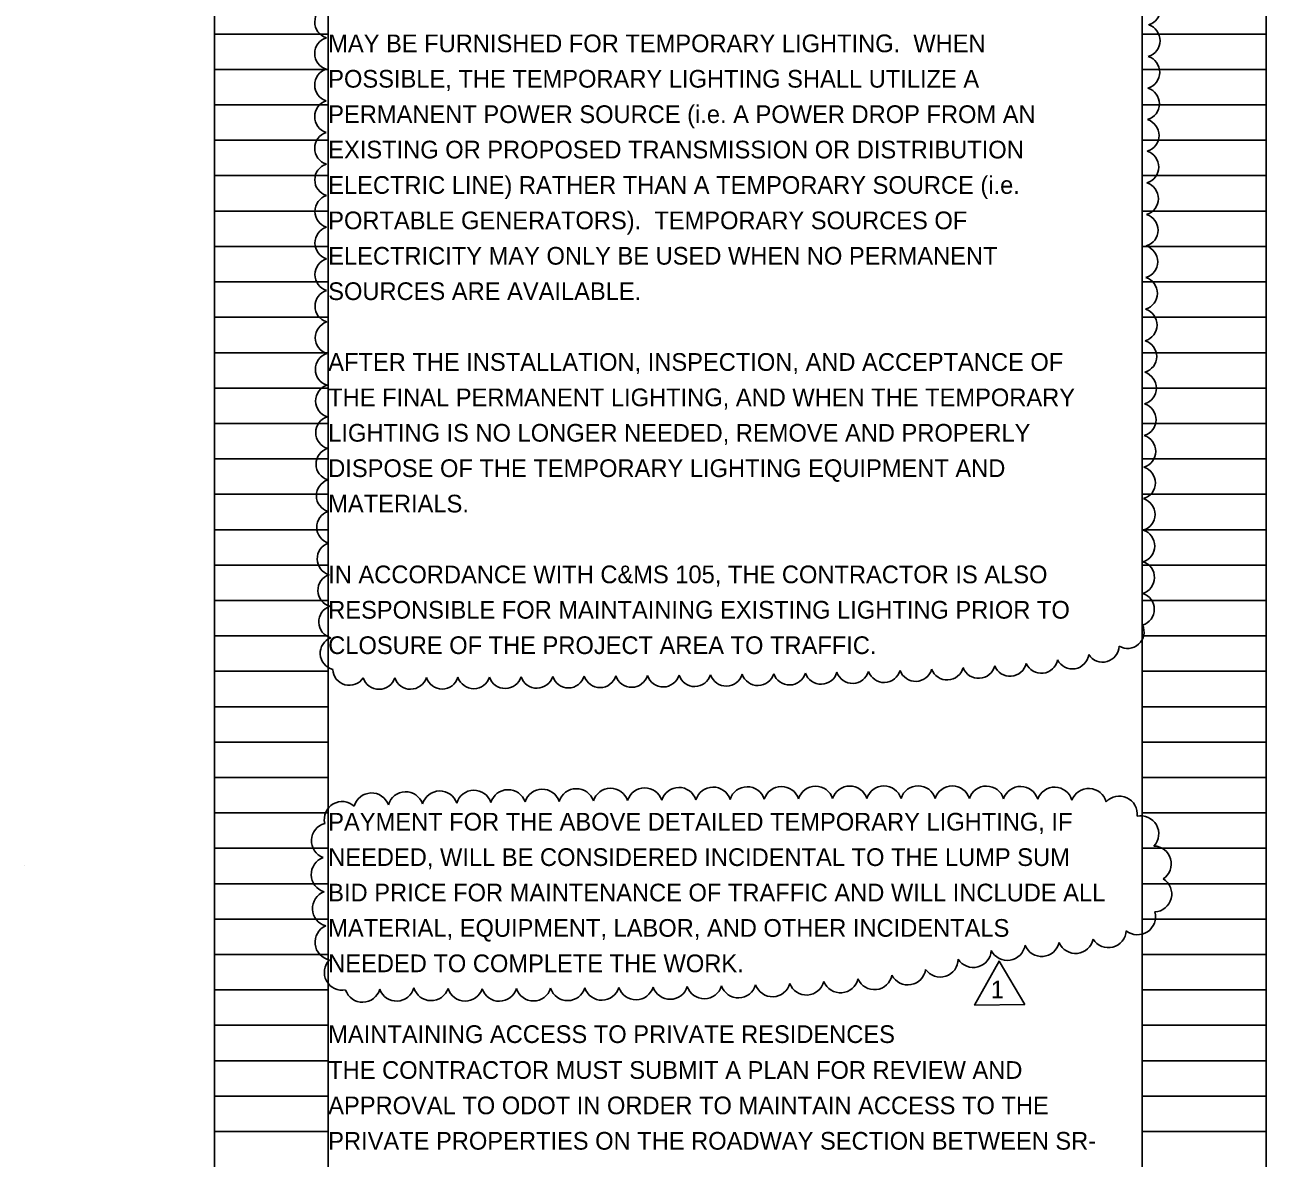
# Model space of a CAD drawing. Extents: x -9 to 32, y -122 to 20.
# Drawn here: x -0.28 to 9.54, y -103.79 to -94.82 of the extents above; entities that cross this region are included whole.
import ezdxf

# ---------------------------------------------------------------- set-up
doc = ezdxf.new("R2010")
doc.units = 0
for name, color, linetype in [('SC_Scratch1', 7, 'Continuous'), ('SC_Scratch2', 7, 'Continuous'), ('SH_Text', 7, 'Continuous')]:
    doc.layers.add(name, color=color, linetype=linetype)

msp = doc.modelspace()

# ---------------------------------------------------------------- linework, layer by layer
at = {"layer": 'SC_Scratch1'}
for p, q in [((1.2158, -100.4944), (1.2158, -80.3344)), ((2.1158, -100.4944), (2.1158, -80.3344)), ((8.5558, -100.4944), (8.5558, -80.3344)), ((9.5358, -100.4944), (9.5358, -80.3344)), ((1.2158, -94.8944), (2.1158, -94.8944)), ((8.5558, -94.8944), (9.5358, -94.8944)), ((1.2158, -95.1744), (2.1158, -95.1744)), ((8.5558, -95.1744), (9.5358, -95.1744)), ((1.2158, -95.4544), (2.1158, -95.4544)), ((8.5558, -95.4544), (9.5358, -95.4544)), ((1.2158, -95.7344), (2.1158, -95.7344)), ((8.5558, -95.7344), (9.5358, -95.7344)), ((1.2158, -96.0144), (2.1158, -96.0144)), ((8.5558, -96.0144), (9.5358, -96.0144)), ((1.2158, -96.2944), (2.1158, -96.2944)), ((8.5558, -96.2944), (9.5358, -96.2944)), ((1.2158, -96.5744), (2.1158, -96.5744)), ((8.5558, -96.5744), (9.5358, -96.5744)), ((1.2158, -96.8544), (2.1158, -96.8544)), ((8.5558, -96.8544), (9.5358, -96.8544)), ((1.2158, -97.1344), (2.1158, -97.1344)), ((8.5558, -97.1344), (9.5358, -97.1344)), ((1.2158, -97.4144), (2.1158, -97.4144)), ((8.5558, -97.4144), (9.5358, -97.4144)), ((1.2158, -97.6944), (2.1158, -97.6944)), ((8.5558, -97.6944), (9.5358, -97.6944)), ((1.2158, -97.9744), (2.1158, -97.9744)), ((8.5558, -97.9744), (9.5358, -97.9744)), ((1.2158, -98.2544), (2.1158, -98.2544)), ((8.5558, -98.2544), (9.5358, -98.2544)), ((1.2158, -98.5344), (2.1158, -98.5344)), ((8.5558, -98.5344), (9.5358, -98.5344)), ((1.2158, -98.8144), (2.1158, -98.8144)), ((8.5558, -98.8144), (9.5358, -98.8144)), ((1.2158, -99.0944), (2.1158, -99.0944)), ((8.5558, -99.0944), (9.5358, -99.0944)), ((1.2158, -99.3744), (2.1158, -99.3744)), ((8.5558, -99.3744), (9.5358, -99.3744)), ((1.2158, -99.6544), (2.1158, -99.6544)), ((8.5558, -99.6544), (9.5358, -99.6544)), ((1.2158, -99.9344), (2.1158, -99.9344)), ((8.5558, -99.9344), (9.5358, -99.9344)), ((1.2158, -100.2144), (2.1158, -100.2144)), ((8.5558, -100.2144), (9.5358, -100.2144)), ((1.2158, -100.4944), (2.1158, -100.4944)), ((1.2158, -120.6544), (1.2158, -100.4944)), ((1.2158, -100.4944), (2.1158, -100.4944)), ((2.1158, -120.6544), (2.1158, -100.4944)), ((8.5558, -100.4944), (9.5358, -100.4944)), ((8.5558, -120.6544), (8.5558, -100.4944)), ((8.5558, -100.4944), (9.5358, -100.4944)), ((9.5358, -120.6544), (9.5358, -100.4944)), ((1.2158, -100.7744), (2.1158, -100.7744)), ((8.5558, -100.7744), (9.5358, -100.7744)), ((1.2158, -101.0544), (2.1158, -101.0544)), ((8.5558, -101.0544), (9.5358, -101.0544)), ((1.2158, -101.3344), (2.1158, -101.3344)), ((8.5558, -101.3344), (9.5358, -101.3344)), ((-0.2842, -101.4744), (-0.2842, -101.4744)), ((1.2158, -101.6144), (2.1158, -101.6144)), ((8.5558, -101.6144), (9.5358, -101.6144)), ((1.2158, -101.8944), (2.1158, -101.8944)), ((8.5558, -101.8944), (9.5358, -101.8944)), ((1.2158, -102.1744), (2.1158, -102.1744)), ((8.5558, -102.1744), (9.5358, -102.1744)), ((1.2158, -102.4544), (2.1158, -102.4544)), ((8.5558, -102.4544), (9.5358, -102.4544)), ((1.2158, -102.7344), (2.1158, -102.7344)), ((8.5558, -102.7344), (9.5358, -102.7344)), ((1.2158, -103.0144), (2.1158, -103.0144)), ((8.5558, -103.0144), (9.5358, -103.0144)), ((1.2158, -103.2944), (2.1158, -103.2944)), ((8.5558, -103.2944), (9.5358, -103.2944)), ((1.2158, -103.5744), (2.1158, -103.5744)), ((8.5558, -103.5744), (9.5358, -103.5744))]:
    msp.add_line(p, q, dxfattribs=at)
at = {"layer": 'SC_Scratch2'}
msp.add_lwpolyline([(7.627, -102.5692), (7.4228, -102.2269), (7.2285, -102.5749)], close=True, dxfattribs=at)
for centre, radius, start, end in [((8.5682, -94.696), 0.131, 286.87145, 71.87145), ((2.1406, -94.7981), 0.131, 107.45003, 252.45003), ((8.5655, -94.9459), 0.131, 286.87281, 71.87281), ((2.1404, -95.048), 0.131, 107.46931, 252.46931), ((8.5628, -95.1957), 0.131, 286.87428, 71.87428), ((2.1403, -95.2978), 0.131, 107.49011, 252.49011), ((8.5601, -95.4456), 0.131, 286.87588, 71.87588), ((2.1403, -95.5477), 0.131, 107.51264, 252.51264), ((8.5573, -95.6954), 0.131, 286.87764, 71.87764), ((2.1404, -95.7975), 0.131, 107.53717, 252.53717), ((8.5546, -95.9452), 0.131, 286.87957, 71.87957), ((2.1407, -96.0473), 0.131, 107.56399, 252.56399), ((8.5519, -96.1951), 0.131, 286.88171, 71.88171), ((2.141, -96.2971), 0.131, 107.5935, 252.5935), ((8.5492, -96.4449), 0.131, 286.88411, 71.88411), ((2.1415, -96.547), 0.131, 107.62618, 252.62618), ((8.5466, -96.6947), 0.131, 286.88681, 71.88681), ((2.1421, -96.7968), 0.131, 107.66264, 252.66264), ((8.5439, -96.9446), 0.131, 286.8899, 71.8899), ((2.1429, -97.0466), 0.131, 107.70366, 252.70366), ((8.5412, -97.1944), 0.131, 286.89345, 71.89345), ((2.1439, -97.2964), 0.131, 107.75028, 252.75028), ((8.5386, -97.4443), 0.131, 286.89762, 71.89762), ((2.1451, -97.5462), 0.131, 107.80393, 252.80393), ((8.536, -97.6941), 0.131, 286.9026, 71.9026), ((2.1466, -97.7961), 0.131, 107.86654, 252.86654), ((8.5334, -97.9439), 0.131, 286.90869, 71.90869), ((2.1483, -98.0458), 0.131, 107.94094, 252.94094), ((8.5308, -98.1938), 0.131, 286.91638, 71.91638), ((2.1505, -98.2956), 0.131, 108.03138, 253.03138), ((8.5283, -98.4436), 0.131, 286.92652, 71.92652), ((2.153, -98.5454), 0.131, 108.1446, 253.1446), ((8.5258, -98.6935), 0.131, 286.94079, 71.94079), ((2.1561, -98.7951), 0.131, 108.29214, 253.29214), ((8.5234, -98.9433), 0.131, 286.96309, 71.96309), ((2.16, -99.0448), 0.131, 108.49593, 253.49593), ((8.5212, -99.1932), 0.131, 287.00605, 72.00605), ((2.1651, -99.2944), 0.131, 108.80455, 253.80455), ((8.5194, -99.4433), 0.1311, 287.20429, 72.20429), ((2.1719, -99.5437), 0.131, 109.35948, 254.35948), ((8.4391, -99.6227), 0.1309, 239.469, 24.469), ((2.1836, -99.7922), 0.131, 111.00405, 256.00405), ((8.2417, -99.7312), 0.131, 213.16392, 358.16392), ((7.7572, -99.8193), 0.131, 203.81392, 348.81392), ((8.0023, -99.785), 0.131, 207.13505, 352.13505), ((2.2828, -99.9146), 0.131, 182.04858, 327.04858), ((4.7657, -99.9272), 0.131, 198.1433, 343.1433), ((5.0155, -99.9241), 0.131, 198.25059, 343.25059), ((5.2652, -99.9206), 0.131, 198.37489, 343.37489), ((5.5149, -99.9165), 0.131, 198.51656, 343.51656), ((5.7646, -99.9117), 0.131, 198.68007, 343.68007), ((6.0143, -99.9061), 0.131, 198.87168, 343.87168), ((6.2639, -99.8997), 0.131, 199.10047, 344.10047), ((6.5134, -99.8921), 0.131, 199.38031, 344.38031), ((6.7629, -99.8831), 0.131, 199.73353, 344.73353), ((7.0122, -99.8724), 0.131, 200.19915, 345.19915), ((7.2612, -99.8592), 0.131, 200.85334, 345.85334), ((7.5098, -99.8424), 0.131, 201.87283, 346.87283), ((2.5175, -99.9462), 0.131, 197.61667, 342.61667), ((2.7672, -99.9453), 0.131, 197.80787, 342.80787), ((3.017, -99.9437), 0.131, 197.9041, 342.9041), ((3.2668, -99.9418), 0.131, 197.96486, 342.96486), ((3.5166, -99.9397), 0.131, 198.00773, 343.00773), ((3.7665, -99.9374), 0.131, 198.04006, 343.04006), ((4.0163, -99.935), 0.131, 198.06559, 343.06559), ((4.2661, -99.9325), 0.131, 198.0864, 343.0864), ((4.5159, -99.9299), 0.131, 198.10379, 343.10379), ((5.1605, -100.9921), 0.1417, 18.07627, 163.07627), ((5.4308, -100.9895), 0.1417, 18.02238, 163.02238), ((5.7011, -100.9872), 0.1417, 17.95167, 162.95167), ((5.9714, -100.9853), 0.1417, 17.86945, 162.86945), ((6.2417, -100.9838), 0.1417, 17.77221, 162.77221), ((6.512, -100.9828), 0.1417, 17.65473, 162.65473), ((6.7823, -100.9824), 0.1417, 17.50882, 162.50882), ((7.0525, -100.9828), 0.1417, 17.32078, 162.32078), ((7.3227, -100.9842), 0.1417, 17.0653, 162.0653), ((7.5927, -100.9872), 0.1417, 16.68881, 161.68881), ((7.8626, -100.9925), 0.1417, 16.04803, 161.04803), ((2.4585, -101.0387), 0.1418, 19.85332, 164.85332), ((2.7282, -101.0294), 0.1418, 19.08118, 164.08118), ((2.9983, -101.0228), 0.1417, 18.75707, 163.75707), ((3.2684, -101.0173), 0.1417, 18.56572, 163.56572), ((3.5387, -101.0126), 0.1417, 18.43554, 163.43554), ((3.8089, -101.0084), 0.1417, 18.33957, 163.33957), ((4.0792, -101.0046), 0.1417, 18.26501, 163.26501), ((4.3495, -101.0011), 0.1417, 18.20493, 163.20493), ((4.6199, -100.9979), 0.1417, 18.15517, 163.15517), ((4.8902, -100.9949), 0.1417, 18.11307, 163.11307), ((8.1316, -101.0029), 0.1418, 14.50028, 159.50028), ((8.3735, -101.063), 0.1417, 352.62922, 137.62922), ((2.2264, -101.1065), 0.1417, 47.71182, 192.71182), ((2.1252, -101.2745), 0.1418, 105.14291, 250.14291), ((8.5437, -101.2198), 0.1418, 317.07667, 102.07667), ((8.6438, -101.458), 0.1417, 303.49257, 88.49257), ((2.123, -101.5419), 0.1417, 108.92527, 253.92527), ((8.6472, -101.6966), 0.1417, 273.15388, 58.15388), ((2.1324, -101.8112), 0.1417, 110.07051, 255.07051), ((8.5186, -101.8766), 0.1417, 230.76206, 15.76206), ((2.1532, -102.0778), 0.1417, 113.85293, 258.85293), ((8.2874, -101.9788), 0.1417, 211.91968, 356.91968), ((7.4882, -102.0798), 0.1417, 206.53849, 351.53849), ((7.7601, -102.0481), 0.1417, 201.76188, 346.76188), ((8.0283, -102.0248), 0.1417, 203.19425, 348.19425), ((2.2271, -102.316), 0.1417, 135.61372, 280.61372), ((6.9579, -102.2109), 0.1417, 215.02182, 0.02182), ((7.2199, -102.1357), 0.1417, 211.99209, 356.99209), ((6.7013, -102.2734), 0.1417, 207.38589, 352.38589), ((5.0908, -102.3826), 0.1417, 198.64889, 343.64889), ((5.3607, -102.376), 0.1417, 199.16249, 344.16249), ((5.6304, -102.3666), 0.1417, 199.81195, 344.81195), ((5.8998, -102.3537), 0.1417, 200.66996, 345.66996), ((6.1687, -102.336), 0.1417, 201.87876, 346.87876), ((6.4364, -102.311), 0.1417, 203.76864, 348.76864), ((2.3875, -102.41), 0.1417, 198.67141, 343.67141), ((2.6568, -102.4015), 0.1417, 199.93496, 344.93496), ((2.9295, -102.3979), 0.1417, 196.56311, 341.56311), ((3.1996, -102.4017), 0.1417, 196.85483, 341.85483), ((3.4693, -102.4024), 0.1417, 197.80771, 342.80771), ((3.7395, -102.4005), 0.1417, 198.0277, 343.0277), ((4.0098, -102.3977), 0.1417, 198.14319, 343.14319), ((4.2801, -102.3945), 0.1417, 198.21745, 343.21745), ((4.5504, -102.391), 0.1417, 198.27039, 343.27039), ((4.8207, -102.3872), 0.1417, 198.32339, 343.32339)]:
    msp.add_arc(centre, radius, start, end, dxfattribs=at)

# ---------------------------------------------------------------- texts
msp.add_text('1', height=0.14, dxfattribs=at).set_placement((7.3574, -102.521))
at = {"layer": 'SH_Text'}
for s, p in [('MAY BE FURNISHED FOR TEMPORARY LIGHTING.  WHEN ', (2.1158, -95.0381)), ('POSSIBLE, THE TEMPORARY LIGHTING SHALL UTILIZE A ', (2.1158, -95.3181)), ('PERMANENT POWER SOURCE (i.e. A POWER DROP FROM AN ', (2.1158, -95.5981)), ('EXISTING OR PROPOSED TRANSMISSION OR DISTRIBUTION ', (2.1158, -95.8781)), ('ELECTRIC LINE) RATHER THAN A TEMPORARY SOURCE (i.e. ', (2.1158, -96.1581)), ('PORTABLE GENERATORS).  TEMPORARY SOURCES OF ', (2.1158, -96.4381)), ('ELECTRICITY MAY ONLY BE USED WHEN NO PERMANENT ', (2.1158, -96.7181)), ('SOURCES ARE AVAILABLE.  ', (2.1158, -96.9981)), ('AFTER THE INSTALLATION, INSPECTION, AND ACCEPTANCE OF ', (2.1158, -97.5581)), ('THE FINAL PERMANENT LIGHTING, AND WHEN THE TEMPORARY ', (2.1158, -97.8381)), ('LIGHTING IS NO LONGER NEEDED, REMOVE AND PROPERLY ', (2.1158, -98.1181)), ('DISPOSE OF THE TEMPORARY LIGHTING EQUIPMENT AND ', (2.1158, -98.3981)), ('MATERIALS. ', (2.1158, -98.6781)), ('IN ACCORDANCE WITH C&MS 105, THE CONTRACTOR IS ALSO ', (2.1158, -99.2381)), ('RESPONSIBLE FOR MAINTAINING EXISTING LIGHTING PRIOR TO ', (2.1158, -99.5181)), ('CLOSURE OF THE PROJECT AREA TO TRAFFIC.', (2.1158, -99.7981)), ('PAYMENT FOR THE ABOVE DETAILED TEMPORARY LIGHTING, IF ', (2.1158, -101.1944)), ('NEEDED, WILL BE CONSIDERED INCIDENTAL TO THE LUMP SUM ', (2.1158, -101.4744)), ('BID PRICE FOR MAINTENANCE OF TRAFFIC AND WILL INCLUDE ALL ', (2.1158, -101.7544)), ('MATERIAL, EQUIPMENT, LABOR, AND OTHER INCIDENTALS ', (2.1158, -102.0344)), ('NEEDED TO COMPLETE THE WORK.', (2.1158, -102.3144)), ('MAINTAINING ACCESS TO PRIVATE RESIDENCES', (2.1158, -102.8744)), ('THE CONTRACTOR MUST SUBMIT A PLAN FOR REVIEW AND ', (2.1158, -103.1581)), ('APPROVAL TO ODOT IN ORDER TO MAINTAIN ACCESS TO THE ', (2.1158, -103.4381)), ('PRIVATE PROPERTIES ON THE ROADWAY SECTION BETWEEN SR-', (2.1158, -103.7181))]:
    msp.add_text(s, height=0.14, dxfattribs=at).set_placement(p)

doc.saveas('drawing.dxf')
